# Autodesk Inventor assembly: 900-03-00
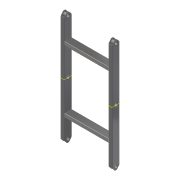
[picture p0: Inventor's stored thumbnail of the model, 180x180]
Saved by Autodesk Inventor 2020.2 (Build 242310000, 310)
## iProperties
Created: 2015-10
Part Number: 900-03-00
Document SubType Name: Konstrukcja spawana
Designer: F.Stasiak
Weld Material: Stal, miękka, spawana
Mass: 61455.7 g
Surface Area: 32689.2 cm^2
Volume: 8087.81 cm^3
Density: 7.59856 g/cm^3
Catalog Web Link: www.expertbooks.pl
Manager: www.cadconsulting.pl
Company: Fabian Stasiak CAD Consulting
Author: F.Stasiak
Subject: Zbiór ćwiczeń. Autodesk Inventor 2020. Kurs Professional
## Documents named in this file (4)
- C:\2020_Kurs_Professional\R3 Dynamika\Komponenty_dyn\900-03-00.iam
- C:\2020_Kurs_Professional\R3 Dynamika\Komponenty_dyn\DIN 59 410 - 900-03-04.ipt
- C:\2020_Kurs_Professional\R3 Dynamika\Komponenty_dyn\900-03-02.ipt
- C:\2020_Kurs_Professional\R3 Dynamika\Komponenty_dyn\DIN 59 410 - 900-03-03.ipt
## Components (10 placed, 3 different names)
1. DIN 59 410 - 900-03-04:1 — Zestawiający:24, Zestawiający:19, Zestawiający:1, Zestawiający:2, Zestawiający:3, Zestawiający:4, Zestawiający:5, Zestawiający:6, Zestawiający:20, Równoległy:1, Zestawiający:22
2. 900-03-02:1 — Zestawiający:1, Zestawiający:2, Zestawiający:7, Zestawiający:17, Zestawiający:21
3. 900-03-02:2 — Zestawiający:3, Zestawiający:4, Zestawiający:7, Zestawiający:8
4. 900-03-02:3 — Zestawiający:5, Zestawiający:6, Zestawiający:8, Zestawiający:18
5. DIN 59 410 - 900-03-04:2 — Zestawiający:9, Zestawiający:10, Zestawiający:11, Zestawiający:12, Zestawiający:13, Zestawiający:14, Zestawiający:19
6. 900-03-02:4 — Zestawiający:9, Zestawiający:10, Zestawiający:15, Zestawiający:17
7. 900-03-02:5 — Zestawiający:11, Zestawiający:12, Zestawiający:15, Zestawiający:16
8. 900-03-02:6 — Zestawiający:13, Zestawiający:14, Zestawiający:16, Zestawiający:18, Zestawiający:23
9. DIN 59 410 - 900-03-03:1 — Zestawiający:20, Równoległy:1, Zestawiający:21, Równoległy:2
10. DIN 59 410 - 900-03-03:2 — Równoległy:2, Zestawiający:22, Zestawiający:23
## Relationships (26: Mate 24, Flush 2)
- Zestawiający:24 [Mate]: DIN 59 410 - 900-03-04:1
- Zestawiający:19 [Mate]: DIN 59 410 - 900-03-04:1 ↔ DIN 59 410 - 900-03-04:2
- Zestawiający:1 [Mate]: DIN 59 410 - 900-03-04:1 ↔ 900-03-02:1
- Zestawiający:2 [Mate]: DIN 59 410 - 900-03-04:1 ↔ 900-03-02:1
- Zestawiający:3 [Mate]: DIN 59 410 - 900-03-04:1 ↔ 900-03-02:2
- Zestawiający:4 [Mate]: DIN 59 410 - 900-03-04:1 ↔ 900-03-02:2
- Zestawiający:5 [Mate]: DIN 59 410 - 900-03-04:1 ↔ 900-03-02:3
- Zestawiający:6 [Mate]: DIN 59 410 - 900-03-04:1 ↔ 900-03-02:3
- Zestawiający:7 [Mate]: 900-03-02:1 ↔ 900-03-02:2
- Zestawiający:8 [Mate]: 900-03-02:2 ↔ 900-03-02:3
- Zestawiający:9 [Mate]: DIN 59 410 - 900-03-04:2 ↔ 900-03-02:4
- Zestawiający:10 [Mate]: DIN 59 410 - 900-03-04:2 ↔ 900-03-02:4
- Zestawiający:11 [Mate]: DIN 59 410 - 900-03-04:2 ↔ 900-03-02:5
- Zestawiający:12 [Mate]: DIN 59 410 - 900-03-04:2 ↔ 900-03-02:5
- Zestawiający:13 [Mate]: DIN 59 410 - 900-03-04:2 ↔ 900-03-02:6
- Zestawiający:14 [Mate]: DIN 59 410 - 900-03-04:2 ↔ 900-03-02:6
- Zestawiający:15 [Mate]: 900-03-02:4 ↔ 900-03-02:5
- Zestawiający:16 [Mate]: 900-03-02:5 ↔ 900-03-02:6
- Zestawiający:17 [Mate]: 900-03-02:1 ↔ 900-03-02:4
- Zestawiający:18 [Mate]: 900-03-02:3 ↔ 900-03-02:6
- Zestawiający:20 [Mate]: DIN 59 410 - 900-03-04:1 ↔ DIN 59 410 - 900-03-03:1
- Równoległy:1 [Flush]: DIN 59 410 - 900-03-04:1 ↔ DIN 59 410 - 900-03-03:1
- Zestawiający:21 [Mate]: 900-03-02:1 ↔ DIN 59 410 - 900-03-03:1
- Równoległy:2 [Flush]: DIN 59 410 - 900-03-03:1 ↔ DIN 59 410 - 900-03-03:2
- Zestawiający:22 [Mate]: DIN 59 410 - 900-03-04:1 ↔ DIN 59 410 - 900-03-03:2
- Zestawiający:23 [Mate]: 900-03-02:6 ↔ DIN 59 410 - 900-03-03:2
